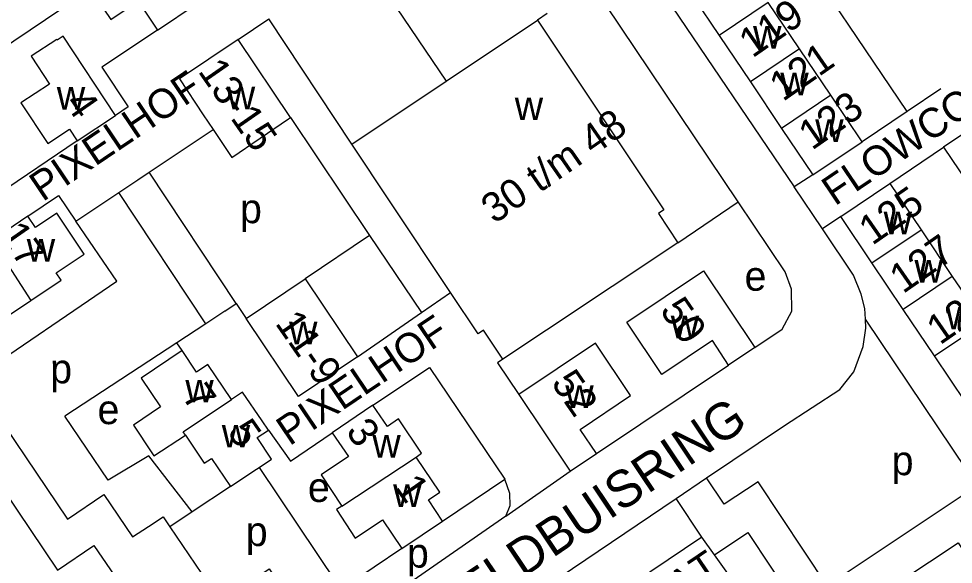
# Model space of a CAD drawing. Extents: x 158356 to 159894, y 383831 to 385260.
# Drawn here: x 159064.9 to 159192, y 384580.8 to 384655 of the extents above; entities that cross this region are included whole.
import ezdxf

# ---------------------------------------------------------------- set-up
doc = ezdxf.new("R2010")
doc.units = 0
for name, color, linetype in [('BLT_Basislijn', 7, 'Continuous'), ('BLT_Bebouwing', 7, 'Continuous'), ('BLT_Centroide', 7, 'Continuous'), ('BLT_Huisnummer', 7, 'Continuous'), ('BLT_Huisnummer_ tussenligend', 7, 'Continuous'), ('BLT_Huisnummer_reeks', 7, 'Continuous'), ('BLT_Onderverdeling_panden', 7, 'Continuous'), ('BLT_Straatnaam', 7, 'Continuous'), ('BLT_Straatnaam_verkleind', 7, 'Continuous'), ('BLT_Vlakafsluiter', 7, 'Continuous')]:
    doc.layers.add(name, color=color, linetype=linetype)

msp = doc.modelspace()

# ---------------------------------------------------------------- linework, layer by layer
at = {"layer": 'BLT_Basislijn'}
for p, q in [((159144.8, 384669.86), (159170.36, 384632.09)), ((159111.5, 384663.57), (159123.01, 384646.47)), ((159074.64, 384658.99), (159028.73, 384627.82)), ((159136.77, 384655.66), (159135.45, 384654.74)), ((159094.72, 384652.11), (159098.89, 384654.96)), ((159110.18, 384637.92), (159098.89, 384654.96)), ((159190.3, 384645.42), (159185.72, 384642.35)), ((159185.72, 384642.35), (159179.6, 384638.23)), ((159082.65, 384634.1), (159091.35, 384639.9)), ((159072.82, 384638.35), (159058.63, 384628.73)), ((159183.38, 384632.57), (159190.69, 384637.51)), ((159081.1, 384633.07), (159082.65, 384634.1)), ((159094.49, 384616.24), (159082.65, 384634.1)), ((159078.49, 384631.33), (159081.1, 384633.07)), ((159172.9, 384633.73), (159170.36, 384632.09)), ((159072.66, 384627.45), (159078.49, 384631.33)), ((159090.32, 384613.47), (159078.49, 384631.33)), ((159154.55, 384624.5), (159162.76, 384630.05)), ((159176.71, 384628.08), (159174.22, 384626.4)), ((159112.62, 384625.49), (159119.66, 384615)), ((159119.66, 384615), (159123.63, 384617.73)), ((159092.94, 384615.21), (159094.49, 384616.24)), ((159094.49, 384616.24), (159095.85, 384614.21)), ((159092.94, 384615.21), (159090.32, 384613.47)), ((159110.95, 384609), (159119.66, 384615)), ((159090.32, 384613.47), (159086.41, 384610.88)), ((159086.41, 384610.88), (159071.16, 384600.93)), ((159087.11, 384609.83), (159086.41, 384610.88)), ((159143.49, 384595.83), (159161.44, 384607.88)), ((159122.55, 384586.67), (159131, 384592.35)), ((159154.32, 384589.73), (159158.46, 384592.52)), ((159160.83, 384588.95), (159158.46, 384592.52)), ((159093.7, 384591.36), (159088.46, 384587.9)), ((159117.25, 384564.77), (159154.32, 384589.73)), ((159157.79, 384584.49), (159154.32, 384589.73)), ((159088.46, 384587.9), (159085.45, 384585.9)), ((159131.14, 384587.35), (159111.28, 384573.55)), ((159159.52, 384582.08), (159157.79, 384584.49)), ((159117, 384582.93), (159108.72, 384577.37)), ((159162.5, 384577.95), (159159.52, 384582.08))]:
    msp.add_line(p, q, dxfattribs=at)
for points in [[(159185.72, 384642.35), (159168.85, 384667.41), (159170.09, 384668.24)], [(159162.76, 384630.05), (159142.78, 384659.8)], [(159083.76, 384653.41), (159076.2, 384648.35), (159079.78, 384642.98), (159078.04, 384641.8)], [(159101.85, 384641.53), (159112.62, 384625.49)], [(159066.12, 384628.11), (159070.3, 384630.93), (159072.66, 384627.45)], [(159165.02, 384610.28), (159168.73, 384612.77), (159170.07, 384615.22), (159170.02, 384618.21), (159169.14, 384620.55), (159162.76, 384630.05)], [(159058.64, 384605.97), (159078.23, 384619.28), (159072.66, 384627.45)], [(159180.06, 384614.13), (159179.97, 384615.56), (159179.47, 384617.5), (159178.46, 384620.08), (159174.22, 384626.4)], [(159112.62, 384625.49), (159103.84, 384619.6)], [(159158.46, 384592.52), (159169.04, 384599.64), (159176.6, 384604.53), (159178.49, 384606.96), (159179.76, 384610.39), (159180.13, 384612.91), (159180.06, 384614.13)], [(159205.96, 384584.63), (159201.78, 384581.82), (159180.06, 384614.13)], [(159130.74, 384608.66), (159130.02, 384608.17), (159132.92, 384603.85)], [(159113.08, 384602.42), (159120.78, 384607.56)], [(159120.78, 384607.56), (159131, 384592.35)], [(159058.64, 384605.97), (159071.51, 384586.94), (159076.46, 384590.29), (159080.38, 384584.5), (159082.55, 384585.94)], [(159047.22, 384598.27), (159051.21, 384600.98), (159053.99, 384596.84), (159057.29, 384599.05), (159070.17, 384580), (159075.12, 384583.35), (159079.03, 384577.58)], [(159088.46, 384587.9), (159082.61, 384595.52), (159077.07, 384592.21), (159071.16, 384600.93)], [(159098.88, 384599.04), (159101.84, 384594.8), (159107.52, 384598.68)], [(159257.08, 384596.26), (159227.83, 384576.27), (159221.79, 384585.31), (159205.01, 384574.09), (159194.06, 384590.62), (159174.84, 384577.88), (159165.47, 384592.02), (159160.83, 384588.95)], [(159097.58, 384593.95), (159108.12, 384578.27)], [(159131.14, 384587.35), (159131.74, 384588.76), (159131.7, 384590.41), (159131, 384592.35)], [(159082.55, 384585.94), (159084.52, 384587.26), (159085.45, 384585.9)], [(159085.45, 384585.9), (159092.35, 384575.71), (159098.97, 384580.17), (159102.71, 384574.63), (159108.12, 384578.27)], [(159157.79, 384584.49), (159120.77, 384559.56), (159117.25, 384564.77)], [(159159.52, 384582.08), (159164.07, 384585.09), (159173.44, 384570.95), (159192.66, 384583.69), (159203.62, 384567.15), (159220.41, 384578.37), (159226.45, 384569.34), (159235.48, 384575.5)]]:
    msp.add_lwpolyline(points, dxfattribs=at)
at = {"layer": 'BLT_Bebouwing'}
for p, q in [((159155.92, 384659.01), (159160.17, 384652.69)), ((159171.1, 384650.86), (159166.85, 384657.18)), ((159160.17, 384652.69), (159164.41, 384646.37)), ((159175.35, 384644.55), (159171.1, 384650.86)), ((159164.41, 384646.37), (159168.66, 384640.05)), ((159179.6, 384638.23), (159175.35, 384644.55)), ((159197.33, 384641.97), (159190.69, 384637.51)), ((159168.66, 384640.05), (159172.9, 384633.73)), ((159115.41, 384630.08), (159110.18, 384637.92)), ((159172.9, 384633.73), (159179.6, 384638.23)), ((159190.69, 384637.51), (159195.29, 384630.66)), ((159176.71, 384628.08), (159183.38, 384632.57)), ((159183.38, 384632.57), (159187.63, 384626.25)), ((159180.95, 384621.76), (159176.71, 384628.08)), ((159187.63, 384626.25), (159191.88, 384619.93)), ((159185.2, 384615.44), (159180.95, 384621.76)), ((159191.88, 384619.93), (159196.13, 384613.61)), ((159189.45, 384609.12), (159185.2, 384615.44)), ((159193.7, 384602.8), (159189.45, 384609.12)), ((159093.7, 384591.36), (159096.88, 384593.48))]:
    msp.add_line(p, q, dxfattribs=at)
for points in [[(159074.64, 384658.99), (159077.41, 384654.84), (159081.14, 384657.33), (159083.76, 384653.41)], [(159083.76, 384653.41), (159089.16, 384657.02)], [(159123.01, 384646.47), (159135.45, 384654.74)], [(159135.45, 384654.74), (159152.62, 384628.96), (159151.9, 384628.48), (159154.55, 384624.5)], [(159078.04, 384641.8), (159070.93, 384652.57), (159070.13, 384652.04), (159070.07, 384652.13), (159066.6, 384649.88), (159069.08, 384646.08), (159065.18, 384643.54), (159068.86, 384637.98), (159071.79, 384639.92), (159072.82, 384638.35)], [(159094.72, 384652.11), (159086.74, 384646.77), (159090, 384641.9)], [(159101.85, 384641.53), (159094.72, 384652.11)], [(159110.18, 384637.92), (159123.01, 384646.47)], [(159072.82, 384638.35), (159078.04, 384641.8)], [(159090, 384641.9), (159091.35, 384639.9)], [(159101.6, 384641.36), (159101.85, 384641.53)], [(159091.35, 384639.9), (159093.88, 384636.11), (159101.6, 384641.36)], [(159123.63, 384617.73), (159115.41, 384630.08)], [(159066.12, 384628.11), (159061.21, 384624.82)], [(159066.54, 384616.66), (159070.65, 384619.41), (159069.98, 384620.4), (159073.78, 384622.93), (159070.08, 384628.5), (159067.15, 384626.56), (159066.12, 384628.11)], [(159154.55, 384624.5), (159136.69, 384612.61)], [(159056.09, 384621.4), (159057.11, 384619.86), (159054.21, 384617.9), (159057.95, 384612.35), (159061.73, 384614.87), (159062.42, 384613.9), (159066.54, 384616.66)], [(159161.44, 384607.88), (159159.27, 384611.19), (159152.39, 384606.59), (159147.6, 384613.7), (159158.03, 384620.7), (159165.02, 384610.28)], [(159095.85, 384614.21), (159103.84, 384619.6)], [(159103.84, 384619.6), (159110.95, 384609)], [(159127.37, 384612.11), (159123.63, 384617.73)], [(159102.96, 384603.6), (159095.85, 384614.21)], [(159130.74, 384608.66), (159128.11, 384612.61), (159127.37, 384612.11)], [(159136.69, 384612.61), (159130.74, 384608.66)], [(159087.11, 384609.83), (159081.55, 384606.11), (159084.17, 384602.2), (159080.5, 384599.71), (159083.01, 384595.94)], [(159093.82, 384603.17), (159090.61, 384607.96), (159089.06, 384606.92), (159087.11, 384609.83)], [(159143.49, 384595.83), (159141.26, 384599.12), (159148.12, 384603.72), (159143.35, 384610.85), (159132.92, 384603.85)], [(159165.02, 384610.28), (159161.44, 384607.88)], [(159110.95, 384609), (159102.96, 384603.6)], [(159098.01, 384600.31), (159095.35, 384604.2), (159093.82, 384603.17)], [(159132.92, 384603.85), (159139.92, 384593.44)], [(159113.08, 384602.42), (159107.52, 384598.68)], [(159118.95, 384595.37), (159119.7, 384595.91), (159116.57, 384600.55), (159115.03, 384599.52), (159113.08, 384602.42)], [(159098.88, 384599.04), (159098.01, 384600.31)], [(159083.01, 384595.94), (159083.29, 384595.52), (159087.56, 384598.36)], [(159087.56, 384598.36), (159090.13, 384594.52), (159091.13, 384595.16), (159093.7, 384591.36)], [(159097.58, 384593.95), (159099.27, 384595.08), (159097.32, 384598.01), (159098.88, 384599.04)], [(159107.52, 384598.68), (159109.73, 384595.42), (159106.01, 384592.96), (159108.83, 384588.7)], [(159139.92, 384593.44), (159143.49, 384595.83)], [(159122.55, 384586.67), (159120.62, 384589.57), (159122.15, 384590.61), (159118.95, 384595.37)], [(159096.88, 384593.48), (159097.58, 384593.95)], [(159108.83, 384588.7), (159108.1, 384588.22), (159110.66, 384584.36), (159114.37, 384586.84), (159117, 384582.93)], [(159117, 384582.93), (159122.55, 384586.67)]]:
    msp.add_lwpolyline(points, dxfattribs=at)
at = {"layer": 'BLT_Onderverdeling_panden'}
for p, q in [((159166.85, 384657.18), (159160.16, 384652.69)), ((159171.1, 384650.86), (159164.41, 384646.37)), ((159175.35, 384644.55), (159168.66, 384640.05)), ((159180.95, 384621.76), (159187.63, 384626.25)), ((159191.88, 384619.93), (159185.2, 384615.44)), ((159189.45, 384609.12), (159196.13, 384613.61)), ((159108.83, 384588.7), (159118.95, 384595.37))]:
    msp.add_line(p, q, dxfattribs=at)
for points in [[(159061.21, 384624.82), (159061.21, 384624.82), (159066.54, 384616.66)], [(159087.56, 384598.36), (159087.27, 384598.79), (159093.82, 384603.17)]]:
    msp.add_lwpolyline(points, dxfattribs=at)
at = {"layer": 'BLT_Vlakafsluiter'}
for p, q in [((159174.22, 384626.4), (159170.36, 384632.09)), ((159131.14, 384587.35), (159139.92, 384593.44))]:
    msp.add_line(p, q, dxfattribs=at)

# ---------------------------------------------------------------- texts
at = {"layer": 'BLT_Centroide'}
for s, p in [('w', (159164.78, 384650.89)), ('w', (159168.48, 384644.54)), ('w', (159070.07, 384642.6)), ('w', (159093.19, 384642.64)), ('w', (159132.36, 384641.17)), ('w', (159173.23, 384638.2)), ('p', (159094.99, 384627.16)), ('w', (159182.54, 384625.64)), ('w', (159065.98, 384621.94)), ('e', (159163.62, 384617.98)), ('w', (159186.74, 384619.07)), ('w', (159191.01, 384612.71)), ('w', (159101.66, 384610.7)), ('w', (159153.58, 384611.52)), ('p', (159069.17, 384605.39)), ('w', (159087.55, 384602.79)), ('w', (159139.24, 384602.05)), ('e', (159075.61, 384599.84)), ('w', (159092.51, 384596.67)), ('w', (159112.99, 384595.3)), ('p', (159183.63, 384592.9)), ('e', (159104.22, 384589.26)), ('w', (159115.82, 384588.57)), ('p', (159095.77, 384583.27)), ('p', (159117.7, 384580.34))]:
    msp.add_text(s, height=4, dxfattribs=at).set_placement(p)
at = {"layer": 'BLT_Huisnummer'}
for s, rotation, p in [('121', 34.8063, (159168.83, 384643.61)), ('4', 304.8063, (159071.04, 384643.48)), ('123', 34.8063, (159172.79, 384636.99)), ('125', 34.8063, (159180.99, 384624.06)), ('17', 304.8063, (159062.07, 384625.63)), ('129', 34.8063, (159190.2, 384610.52)), ('50', 304.6109, (159152.01, 384615.31)), ('52', 304.6084, (159137.22, 384605.44)), ('7', 304.8063, (159087, 384603.59)), ('5', 304.8063, (159093.17, 384598.74)), ('3', 304.8063, (159109.28, 384598.86)), ('1', 304.8063, (159115.96, 384591.26))]:
    msp.add_text(s, height=4, rotation=rotation, dxfattribs=at).set_placement(p)
at = {"layer": 'BLT_Huisnummer_ tussenligend'}
for s, p in [('119', (159164.69, 384649.53)), ('127', (159185.17, 384617.49))]:
    msp.add_text(s, height=4, rotation=34.8063, dxfattribs=at).set_placement(p)
at = {"layer": 'BLT_Huisnummer_reeks'}
for s, rotation, p in [('13-15', 304.8063, (159089.19, 384647.81)), ('30 t/m 48', 34.649, (159129.6, 384626.98)), ('11-9', 304.8063, (159099.68, 384613.54))]:
    msp.add_text(s, height=4, rotation=rotation, dxfattribs=at).set_placement(p)
at = {"layer": 'BLT_Straatnaam'}
msp.add_text('BEELDBUISRING', height=5, rotation=33.8882, dxfattribs=at).set_placement((159119.29, 384569.37))
at = {"layer": 'BLT_Straatnaam_verkleind'}
for s, p in [('FLOWCOATSTRAAT', (159175.91, 384629.42)), ('PIXELHOF', (159068.14, 384630)), ('PIXELHOF', (159101.72, 384596.8)), ('CONUSSTRAAT', (159127.11, 384556.97))]:
    msp.add_text(s, height=4, rotation=34, dxfattribs=at).set_placement(p)

doc.saveas('drawing.dxf')
